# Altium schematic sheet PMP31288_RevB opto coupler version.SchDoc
size 431 x 279 mm; Date: Not shown in title block; ApprovedBy: Not shown in title block; CheckedBy: Not shown in title block; Author: Not shown in title block; CompanyName: Not shown in title block; Engineer: Not shown in title block; Organization: Not shown in title block; Address1: Not shown in title block; Address2: Not shown in title block; Address3: Not shown in title block; Address4: Not shown in title block; DocumentNumber: 2; Revision: Use project parameter SCH_Rev; SheetNumber: 2; SheetTotal: 3; PageSetup: Record=PageOptions¦CenterHorizontal=True¦CenterVertical=True¦PrintScale=1.00¦XCorrection=1.00¦YCorrection=1.00¦PrintKind=0¦BorderSize=5000000¦LeftOffset=0¦BottomOffset=0¦Orientation=2¦PaperLength=1000¦PaperWidth=1000¦Scale=100¦PaperSource=15¦PrintQuality=600¦MediaType=1¦DitherType=10¦PaperKind=Letter¦PrintScaleMode=1
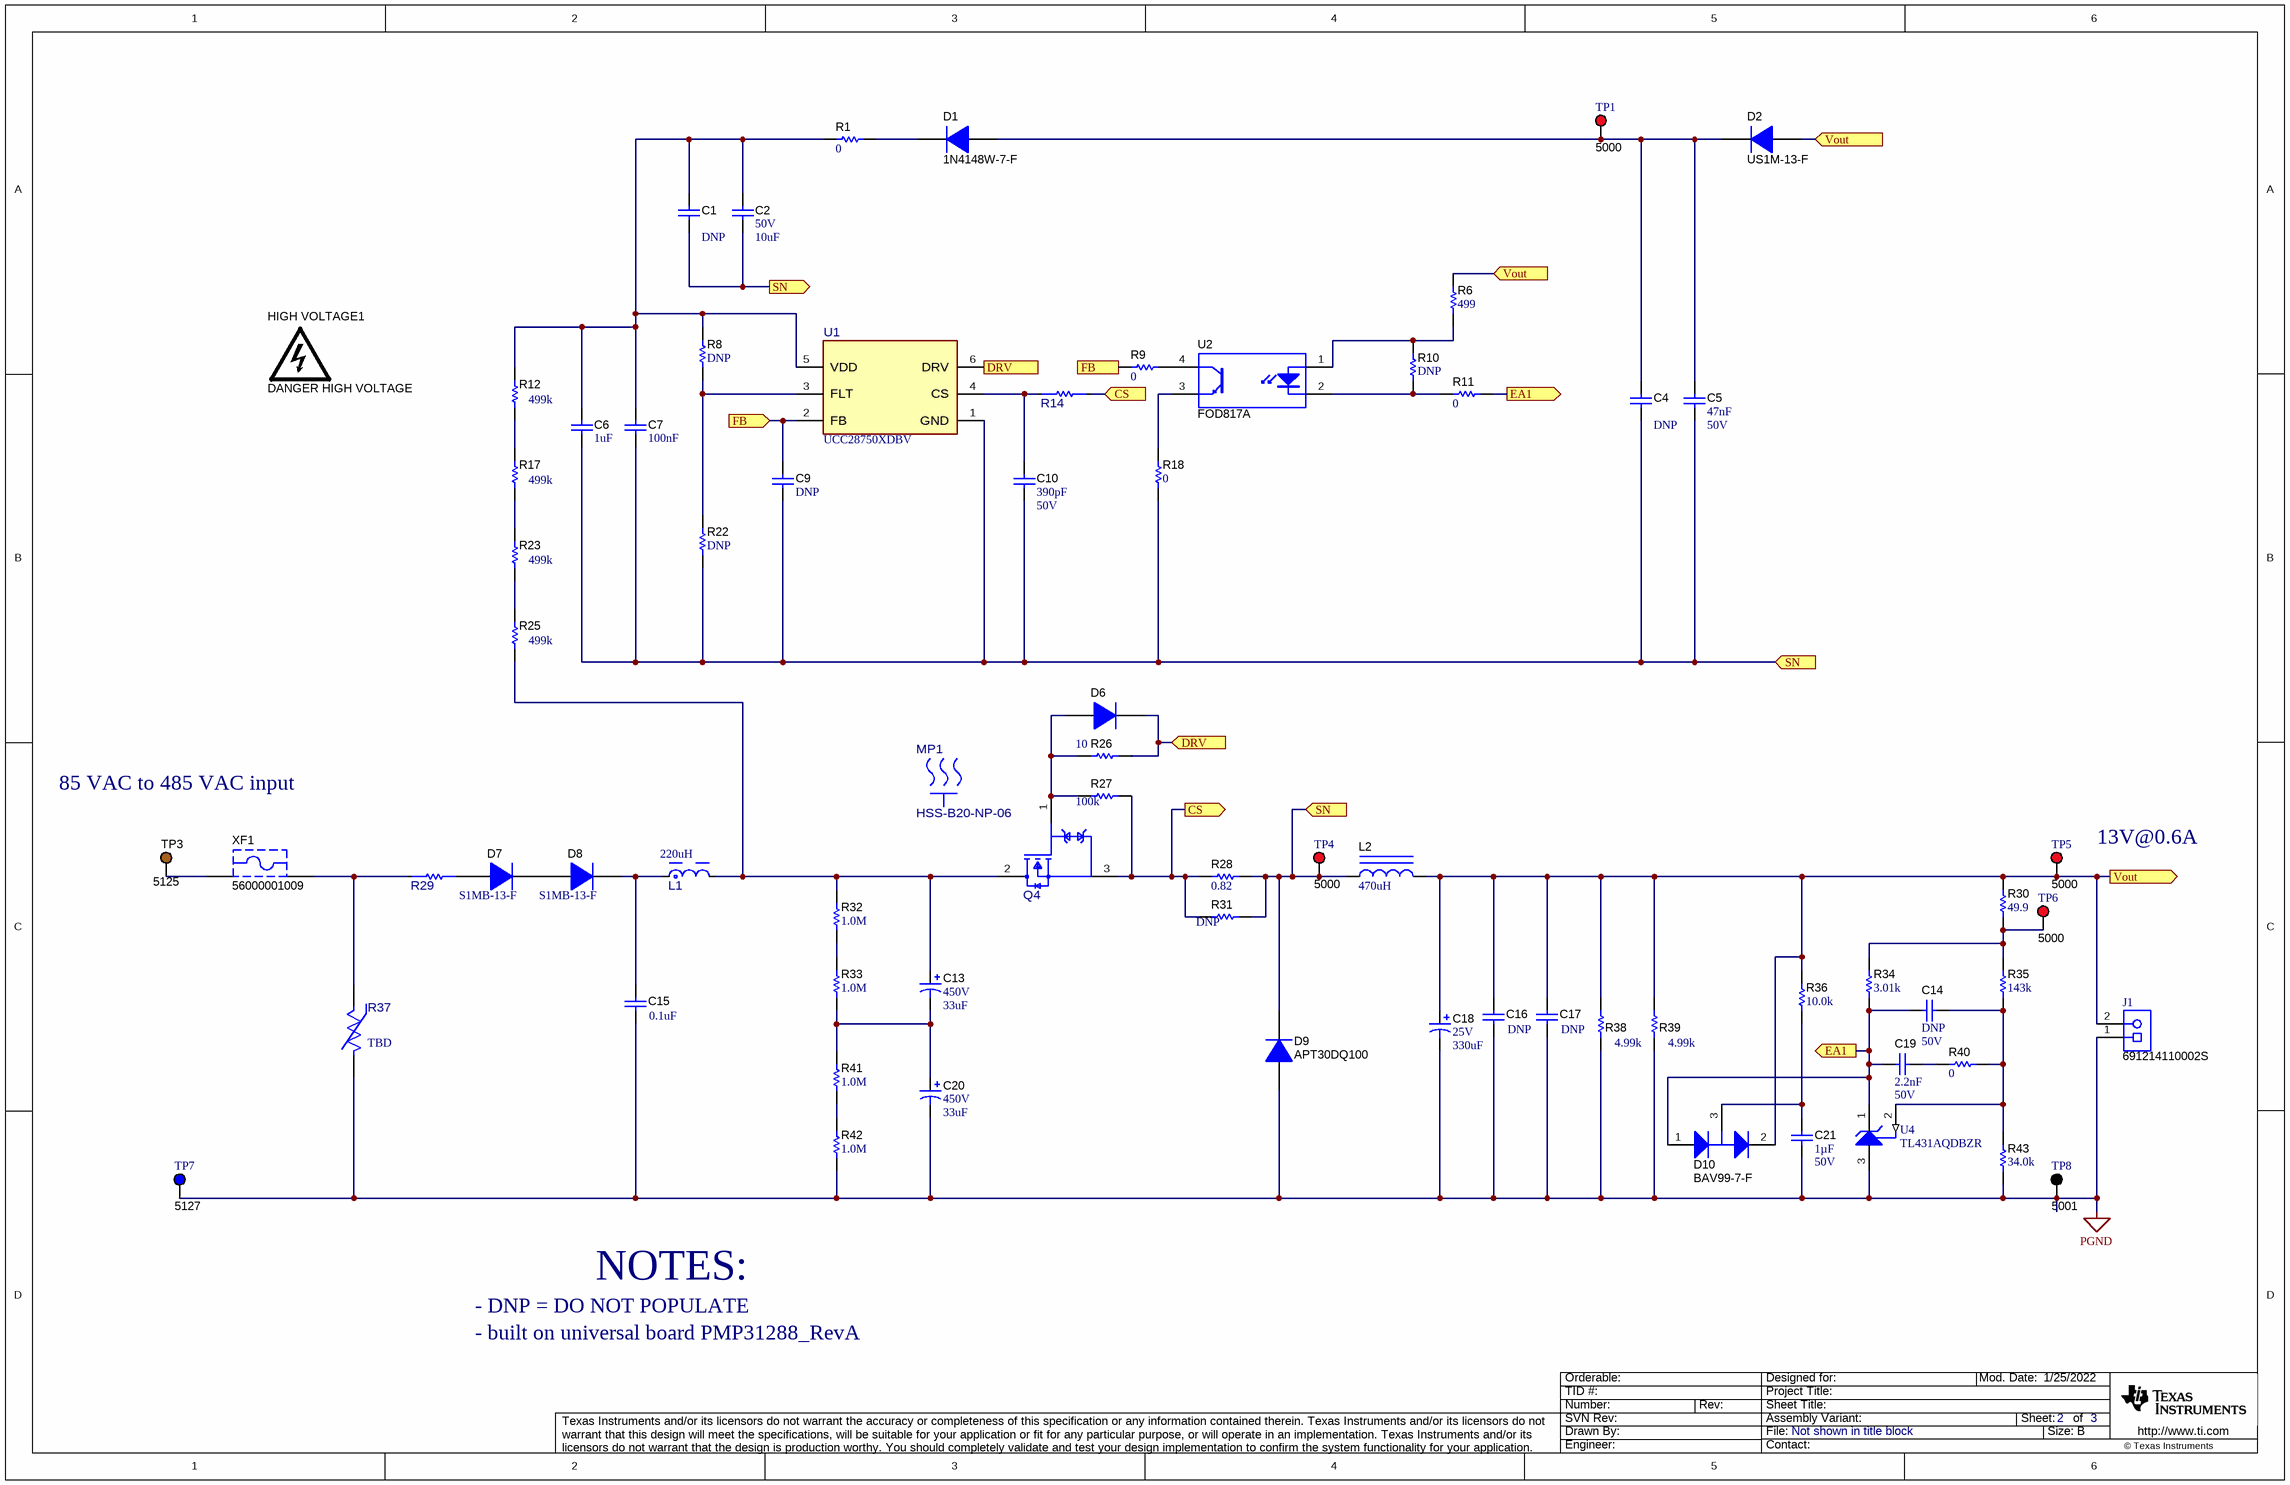
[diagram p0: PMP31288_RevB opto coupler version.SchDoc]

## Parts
C1  ValueDisplayed: DNP  [1210_180]  (hidden comment: DNPC3225X7R1H105K160AA)
C2  VDC_V: 50V  ValueDisplayed: 10uF  [1210_280]  (hidden comment: C3225X7R1H106M250AC)
C4  ValueDisplayed: DNP  [1210_180]  (hidden comment: DNPC3225X7R1H105K160AA)
C5  Cap_F: 47nF  VDC_V: 50V  [0805_HV]  (hidden comment: 08055C473KAT2A)
C6  Cap_F: 1uF  [0805_HV]  (hidden comment: C0805C104J5RACTU)
C7  Cap_F: 100nF  [0805_HV]  (hidden comment: C0805C104J5RACTU)
C9  DNP  [0603]
C10  Cap_F: 390pF  VDC_V: 50V  [0603]  (hidden comment: C0603C391K5RACTU)
C13  VDC_V: 450V  ValueDisplayed: 33uF  [UCS_1800x2000]  (hidden comment: UCS2W330MHD6)
C14  Cap_F: DNP  VDC_V: 50V  [0805_HV]  (hidden comment: DNP08055C473KAT2A)
C15  Cap_F: 0.1uF  [B32913_2650x700x1600]  (hidden comment: B32913C5104K000)
C16  value DNP  [1206]  (hidden comment: GCM31MR71E105KA37L)
C17  value DNP  [1206]  (hidden comment: GCM31MR71E105KA37L)
C18  VDC_V: 25V  ValueDisplayed: 330uF  [SM_RADIAL_F]  (hidden comment: EEE-FK1E331P)
C19  Cap_F: 2.2nF  VDC_V: 50V  [0603]  (hidden comment: GRM188R71H222KA01D)
C20  VDC_V: 450V  ValueDisplayed: 33uF  [UCS_1800x2000]  (hidden comment: UCS2W330MHD6)
C21  Cap_F: 1µF  VDC_V: 50V  [0805_HV]  (hidden comment: GRM21BR71H105KA12L)
D1  1N4148W-7-F  [SOD-123]
D2  US1M-13-F  [SMA]
D6  MMDL914-TP  [SOD-323]  (value not drawn)
D7  S1MB-13-F  [SMB]
D8  S1MB-13-F  [SMB]
D9  APT30DQ100  [TO-247-2]
D10  BAV99-7-F  [SOT-23L]
HIGH_VOLTAGE1  DANGER HIGH VOLTAGE  [IEC_HighVoltage_Small]  (no BOM)
J1  691214110002S  [FP-691214110002S_HDR2-MFG]
L1  value 220uH  [FP-7687480121_RADIAL-MFG]
L2  ValueDisplayed: 470uH  [mss1583]  (hidden comment: MSS1514V-474)
MP1  HSS-B20-NP-06  [FP-HSS-B20-NP-06_HEATSINK_19MM0_9MM52-MFG]
Q4  STP80N240K6  [FP-STP7N105K5_TO-220AB-MFG]  (value not drawn)
R1  ValueDisplayed: 0  [0805_HV]  (hidden comment: CRCW08050000Z0EAHP)
R6  ValueDisplayed: 499  [0603]  (hidden comment: RC0603FR-07499RL)
R8  DNP  [0603]
R9  ValueDisplayed: 0  [0603]  (hidden comment: CRCW06030000Z0EA)
R10  DNP  [0603]
R11  ValueDisplayed: 0  [0603]  (hidden comment: CRCW06030000Z0EA)
R12  value 499k  [1206]  (hidden comment: CRCW1206499KFKEA)
R14  CRCW06031K00FKEAC  [FP-CRCW06031K00FKEAC_0603-MFG]  (value not drawn)
R17  value 499k  [1206]  (hidden comment: CRCW1206499KFKEA)
R18  ValueDisplayed: 0  [0603]  (hidden comment: CRCW06030000Z0EA)
R22  DNP  [0603]
R23  value 499k  [1206]  (hidden comment: CRCW1206499KFKEA)
R25  value 499k  [1206]  (hidden comment: CRCW1206499KFKEA)
R26  value 10  [0805_HV]  (hidden comment: CRCW080510R0JNEA)
R27  value 100k  [0603]  (hidden comment: CRCW0603100KFKEA)
R28  ValueDisplayed: 0.82  [1206]  (hidden comment: ERJ-8RQFR82V)
R29  Z35092238209J6BC10_VM  [FP-Z35092238209J6BC10_VM_AXIAL-MFG]  (value not drawn)
R30  ValueDisplayed: 49.9  [0603]  (hidden comment: RC0603FR-0749R9L)
R31  DNP  [1206]
R32  ValueDisplayed: 1.0M  [1206]  (hidden comment: CRCW12061M00JNEA)
R33  ValueDisplayed: 1.0M  [1206]  (hidden comment: CRCW12061M00JNEA)
R34  ValueDisplayed: 3.01k  [0603]  (hidden comment: RC0603FR-073K01L)
R35  ValueDisplayed: 143k  [0603]  (hidden comment: CRCW0603143KFKEA)
R36  ValueDisplayed: 10.0k  [0603]  (hidden comment: RCG060310K0FKEA)
R37  Part Number: TBD  [FP-V20H510AUTO_RADIAL-MFG]  (hidden comment: V20H510AUTO)
R38  Res_ohm: 4.99k  [FP-CRCW08054K99FKEAHP_0805-IPC_B]  (hidden comment: CRCW08054K99FKEAHP)
R39  Res_ohm: 4.99k  [FP-CRCW08054K99FKEAHP_0805-IPC_B]  (hidden comment: CRCW08054K99FKEAHP)
R40  ValueDisplayed: 0  [0603]  (hidden comment: CRCW06030000Z0EA)
R41  ValueDisplayed: 1.0M  [1206]  (hidden comment: CRCW12061M00JNEA)
R42  ValueDisplayed: 1.0M  [1206]  (hidden comment: CRCW12061M00JNEA)
R43  ValueDisplayed: 34.0k  [0603]  (hidden comment: RC0603FR-0734KL)
TP1  5000  [Keystone5000]
TP3  5125  [Keystone5125]
TP4  5000  [Keystone5000]
TP5  5000  [Keystone5000]
TP6  5000  [Keystone5000]
TP7  5127  [Keystone5127]
TP8  5001  [Keystone5001]
U1  UCC28750XDBV  [DBV0006A-MFG]
U2  FOD817A  [DIP-4]
U4  TL431AQDBZR  [DBZ0003A_N]
XF1  56000001009  [FuseHolder_560000010]

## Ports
CS (in), CS (out), DRV (in), DRV (out), EA1 (out), FB (in), FB (out), SN (in), SN (out), Vout (in), Vout (out)

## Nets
PGND: C15.2 C16.2 C17.2 C18.2(-) C20.2(-) C21.2 D9.2(A) J1.1 R37.1 R38.1 R39.1 R42.1 R43.1 TP7.1 TP8.1 U4.3(ANODE)
CS: Q4.3(S) R14.2 R27.2 R28.1 R31.2 ; port CS
DRV: D6.1(K) R26.2 U1.6(DRV) ; port DRV
EA1: C14.2 C19.2 D10.1(A) R11.1 R34.1 U4.1(CATHODE) ; port EA1
FB: C9.1 R9.2 U1.2(FB) ; port FB
SN: C1.2 C2.2 C4.2 C5.2 C6.2 C7.2 C9.2 C10.2 D9.1(K) L2.1 R18.1 R22.1 R28.2 R31.1 TP4.1 U1.1(GND) ; port SN
Vout: C16.1 C17.1 C18.1(+) D2.2(A) D10.2(K) J1.2 L2.2 R6.2 R30.2 R36.2 R38.2 R39.2 TP5.1 ; port Vout
NetC1_1: C1.1 C2.1 C6.1 C7.1 R1.2 R8.2 R12.2 U1.5(VDD)
NetC4_1: C4.1 C5.1 D1.2(A) D2.1(K) TP1.1
NetC10_1: C10.1 R14.1 U1.4(CS)
NetC13_1: C13.1(+) L1.2 Q4.2(D) R25.1 R32.2
NetC13_2: C13.2(-) C20.1(+) R33.1 R41.2
NetC14_1: C14.1 R35.1 R40.1 R43.2 U4.2(REF)
NetC15_1: C15.1 D8.1(K) L1.1
NetC19_1: C19.1 R40.2
NetC21_1: C21.1 D10.3(C) R36.1
NetD1_1: D1.1(K) R1.1
NetD6_2: D6.2(A) Q4.1(G) R26.1 R27.1
NetD7_1: D7.1(K) D8.2(A)
NetD7_2: D7.2(A) R29.2
NetR6_1: R6.1 R10.2 U2.1(A)
NetR8_1: R8.1 R22.2 U1.3(FLT)
NetR9_1: R9.1 U2.4(C)
NetR10_1: R10.1 R11.2 U2.2(K)
NetR12_1: R12.1 R17.2
NetR17_1: R17.1 R23.2
NetR18_2: R18.2 U2.3(E)
NetR23_1: R23.1 R25.2
NetR29_1: R29.1 R37.2 XF1.1
NetR30_1: R30.1 R34.2 R35.2 TP6.1
NetR32_1: R32.1 R33.2
NetR41_1: R41.1 R42.2
NetTP3_1: TP3.1 XF1.2

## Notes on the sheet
- 85 VAC to 485 VAC input
- (near TP5) 13V@0.6A
- - DNP = DO NOT POPULATE
- NOTES:
- - built on universal board PMP31288_RevA

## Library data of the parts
C1 C4 = CMP-0009119-1: CAP, CERM,; Manufacturer: TDK; TaMin_C: -55°C; ESR_ohm: 7.168m; Polarized: N; TempCo: X7R; SizeAreaWB_mm2: 14.7; Value1: 0.007168 ohm; U/M: EA; Value: DNP; TaMax_C: 125°C; Tolerance_%: 10%; SizeZ_mm: 1.8; SizeX_mm: 3.2; SizeY_mm: 2.5; Value2: 50V; SizeArea_mm2: 8; Cap_F: 1µF; IRMS_A: 2.7503A; AEC Category: Q200
C2 = CMP-0009120-1: CAP, CERM, 10 uF, 50 V, +/- 20%, X7R, 1210; Manufacturer: TDK; TaMin_C: -55°C; Polarized: N; SizeAreaWB_mm2: 14.7; Value1: Unknown; U/M: EA; Value: 10uF; TaMax_C: 125°C; SizeZ_mm: 2.8; SizeX_mm: 3.2; SizeY_mm: 2.5; Cap_Case: 1210; SizeArea_mm2: 8; Cap_F: 10µF; AEC Category: Q200
C5 = CMP-0007659-2: CAP, CERM, 0.047 uF, 50 V, +/- 10%, X7R, 0805; Manufacturer: AVX; TaMin_C: -55°C; ESR_ohm: 35m; Polarized: N; SizeAreaWB_mm2: 6.75; Value1: 0.035 ohm; U/M: EA; TaMax_C: 125°C; SizeZ_mm: 1.45; SizeX_mm: 2; SizeY_mm: 1.25; Cap_Case: 0805; SizeArea_mm2: 2.5; AEC Category: Q200
C6 = CMP-0007721-2: DNP; Manufacturer: Kemet; TaMin_C: -55°C; ESR_ohm: 64m; Polarized: N; TempCo: X7R; SizeAreaWB_mm2: 6.75; Value1: 0.064 ohm; U/M: EA; Value: 1uF; TaMax_C: 125°C; Tolerance_%: 5%; SizeZ_mm: 1.45; SizeX_mm: 2; SizeY_mm: 1.25; Cap_Case: 0805; Value2: 50V; SizeArea_mm2: 2.5; IRMS_A: 1.64A; AEC Category: Q200
C7 = CMP-0007721-2: CAP, CERM, 0.1 uF, 50 V, +/- 5%, X7R, 0805; Manufacturer: Kemet; TaMin_C: -55°C; ESR_ohm: 64m; Polarized: N; SizeAreaWB_mm2: 6.75; Value1: 0.064 ohm; U/M: EA; Value: 0.1uF; TaMax_C: 125°C; SizeZ_mm: 1.45; SizeX_mm: 2; SizeY_mm: 1.25; Cap_Case: 0805; Value2: 50V; SizeArea_mm2: 2.5; IRMS_A: 1.64A; AEC Category: Q200
C9 = CMP-0007144-4: CAP, CERM,; Manufacturer: MuRata; TaMin_C: -55°C; ESR_ohm: 20m; Polarized: N; TempCo: X7R; SizeAreaWB_mm2: 4.68; Value1: 0.02 ohm; U/M: EA; TaMax_C: 125°C; Tolerance_%: 10%; SizeZ_mm: 1; SizeX_mm: 1.6; SizeY_mm: 0.8; Value2: 50V; SizeArea_mm2: 1.28; IRMS_A: 1.84A
C10 = CMP-0006933-5: CAP, CERM, 390 pF, 50 V, +/- 10%, X7R, 0603; Manufacturer: Kemet; TaMin_C: -55°C; Polarized: N; SizeAreaWB_mm2: 4.68; Value1: Unknown; U/M: EA; Value: 390pF; TaMax_C: 125°C; SizeZ_mm: 1; SizeX_mm: 1.6; SizeY_mm: 0.8; SizeArea_mm2: 1.28; AEC Category: Q200
C13 C20 = CMP-0010243-2: CAP, AL, 33 uF, 450 V, +/- 20%, TH; Manufacturer: Nichicon; TaMin_C: -25°C; Polarized: Y; SizeAreaWB_mm2: 400; Value1: Unknown; U/M: EA; Value: 33uF; TaMax_C: 105°C; SizeZ_mm: 21.5; SizeX_mm: 18; Cap_Case: 18x20mm; SizeArea_mm2: 324; CompType: Capacitor; AEC Qualified: N; Cap_F: 33µF; IRMS_A: 980mA; AEC Category: Q200
C14 = CMP-0007659-2: CAP, CERM,; Manufacturer: AVX; TaMin_C: -55°C; ESR_ohm: 35m; Polarized: N; TempCo: X7R; SizeAreaWB_mm2: 6.75; U/M: EA; Value: DNP; TaMax_C: 125°C; Tolerance_%: 10%; SizeZ_mm: 1.45; SizeX_mm: 2; SizeY_mm: 1.25; Cap_Case: 0805; SizeArea_mm2: 2.5; ValueDisplayed: 0.047uF
C15 = CMP-0012372-3: CAP, Film, 0.1 uF, 1000 V, +/- 10%, TH; Manufacturer: TDK; TaMin_C: -40°C; Polarized: N; SizeAreaWB_mm2: 256.5; Value1: Unknown; Value: 0.1uF; TaMax_C: 110°C; SizeZ_mm: 16; SizeX_mm: 26.5; SizeY_mm: 7; Cap_Case: 26.5x7x16mm; Value2: 1000V; SizeArea_mm2: 185.5; VDC_V: 1kV; AEC Category: Q200
C16 C17 = CMP-0008817-1: DNP; Manufacturer: MuRata; TaMin_C: -55°C; Polarized: N; TempCo: X7R; SizeAreaWB_mm2: 10.92; Value1: Unknown; U/M: EA; TaMax_C: 125°C; Tolerance_%: 10%; SizeZ_mm: 1.35; SizeX_mm: 3.2; SizeY_mm: 1.6; Value2: 25V; SizeArea_mm2: 5.12; AEC Qualified: Y; Cap_F: 1µF; AEC Grade: 1; AEC Category: Q200
C18 = CMP-0010717-1: CAP, AL, 330 uF, 25 V, +/- 20%, 0.16 ohm, AEC-Q200 Grade 2, SMD; Manufacturer: Panasonic; TaMin_C: -55°C; ESR_ohm: 0.16; Polarized: Y; SizeAreaWB_mm2: 123.6; U/M: EA; Value: 330uF; TaMax_C: 105°C; SizeZ_mm: 10.2; SizeX_mm: 10; SizeY_mm: 8.3; Cap_Case: F; SizeArea_mm2: 83; CompType: Capacitor; Cap_F: 330µF; IRMS_A: 600mA; AEC Grade: 2; AEC Category: Q200
C19 = CMP-0007443-4: CAP, CERM, 2200 pF, 50 V, +/- 10%, X7R, 0603; Manufacturer: MuRata; TaMin_C: -55°C; Polarized: N; SizeAreaWB_mm2: 4.68; Value1: Unknown; U/M: EA; Value: 2200pF; TaMax_C: 125°C; SizeZ_mm: 1; SizeX_mm: 1.6; SizeY_mm: 0.8; SizeArea_mm2: 1.28; AEC Category: Q200
C21 = CMP-0008350-2: CAP, CERM, 1 uF, 50 V, +/- 10%, X7R, 0805; Manufacturer: MuRata; TaMin_C: -55°C; Polarized: N; SizeAreaWB_mm2: 6.75; Value1: Unknown; U/M: EA; Value: 1uF; TaMax_C: 125°C; SizeZ_mm: 1.45; SizeX_mm: 2; SizeY_mm: 1.25; Cap_Case: 0805; SizeArea_mm2: 2.5; AEC Category: Q200
D1 = CMP-0029001-1: Diode, Ultrafast, 100 V, 0.15 A, SOD-123; Manufacturer: Diodes Inc.; Io_A: 150mA; Green_Lifecycle: Active; SizeAreaWB_mm2: 13.095; Vr_V: 100V; Green_REACh: Passed; Value1: 0.15A; TJmax_C: 150°C; U/M: EA; Value: 100V; SizeZ_mm: 1.35; SizeX_mm: 3.85; SizeY_mm: 1.7; Vf_V: 1.25V; SizeArea_mm2: 6.545; AEC Category: Q101
D2 = CMP-0076882-2: Diode, Ultrafast, 1000 V, 1 A, SMA; Manufacturer: Diodes Inc.; AEC Category: Q101; Value2: 1.7V; SizeZ_mm: 2.87; Green_REACh: Incomplete; Value: 1000V; Value1: 1A; SizeAreaWB_mm2: 37.3428; Green_Lifecycle: Not Set; RJC_CperW: 30.0; SizeX_mm: 5.59; SizeArea_mm2: 16.3228; Vr_V: 1kV; TJmax_C: 150°C; SizeY_mm: 2.92
D6 = CMP-0029045-1: Diode, Switching, 100 V, 0.2 A, SOD-323; Manufacturer: Micro Commercial Components; Io_A: 200mA; Green_Lifecycle: Not Set; SizeAreaWB_mm2: 8.695; Vr_V: 100V; Green_REACh: Incomplete; Value1: 0.2A; TJmax_C: 150°C; U/M: EA; Value: 100V; SizeZ_mm: 1; SizeX_mm: 2.7; SizeY_mm: 1.35; Vf_V: 1V; SizeArea_mm2: 3.645; AEC Category: Q101
D7 D8 = CMP-0077102-2: Diode, Standard Recovery Rectifier, 1000 V, 1 A, SMB; Manufacturer: Diodes Inc.; Vr_V: 1kV; Value1: 1A; SizeZ_mm: 2.6; TJmax_C: 150°C; Vf_V: 1.1V; Value: 1000V; SizeArea_mm2: 21.336; SizeY_mm: 3.81; AEC Category: Q101; AEC Qualified: N; SizeAreaWB_mm2: 44.156; SizeX_mm: 5.6
D9 = CMP-0077054-3: Diode, Ultrafast, 1000 V, 30 A, TH; Manufacturer: Microsemi; Value2: 2.4V; SizeZ_mm: 25.96; Green_Lifecycle: Not Set; SizeAreaWB_mm2: 125.125; AEC Category: Q101; Value: 1000V; TJmax_C: 175°C; SizeY_mm: 5.0; Value1: 30A; Green_REACh: Incomplete; SizeArea_mm2: 79.375; SizeX_mm: 15.875; RJC_CperW: 0.8
D10 = CMP-0076900-2: Diode, Switching, 75 V, 0.3 A, SOT-23; Manufacturer: Diodes Inc.; SizeY_mm: 3.0; Io_A: 300mA; TJmax_C: 150°C; Green_Lifecycle: Active; Vr_V: 75V; Green_REACh: Passed; Vf_V: 1.25V; SizeAreaWB_mm2: 14.0; Value1: 0.3A; SizeX_mm: 2.5; SizeZ_mm: 1.1; Value: 75V; AEC Category: Q101; SizeArea_mm2: 7.5
HIGH_VOLTAGE1 = CMP-0074835-1: IEC 61010-1 High Voltage Warning; SymbolCreator: a0412235
J1 = CMP-0093089-2: 2 Position Wire to Board Terminal Block Horizontal with Board 0.138" (3.50mm) Through Hole; Manufacturer: Wurth; ContactFinish: Tin,Nickel; AEC Qualified: No; Max Wire Gauge: 16; Voltage_V: 300V; SizeZ_mm: 9.2mm; Current_A: 10A; DUT-Pitch_mm: 3.5mm; Min Wire Gauge: 30; Conn Gender: Female; Row_Count: 1; Is Female: yes
L1 = CMP-0095920-1: WE-TI HV Radial Leaded Wire Wound Inductor (High Voltage) 220µH; Manufacturer: Wurth; AEC Qualified: No; Isat: 2A; Tolerance_%: 10%; TaMin_C: -40°C; Test Frequency: 100kHz; DCR_ohm: 0.18; TaMax_C: +85°C; Self Resonant Frequency: 3.1MHz
L2 = CMP-0061946-2: Inductor, Drum Core, Ferrite, 470 uH,; Manufacturer: Coilcraft; Isat: 2.2A @ 30% inductance drop; Irms: 1.35A @ 40C rise; Green_Lifecycle: Not Set; SizeAreaWB_mm2: 292.41; Green_REACh: Incomplete; Value: 470uH; SizeZ_mm: 8.6; SizeX_mm: 15.1; Value2: 1.35A; SizeArea_mm2: 228.01; Ind_H: 470µH; AEC Qualified: N
MP1 = CMP-0091664-1: Heat Sink TO-220 Aluminum 2.9W @ 75°C Board Level; Manufacturer: CUI Devices; AEC Qualified: No; Thermal Resistance Forced Air Flow: 5.84°C/W; Natural Thermal Resistance: 31.94°C/W; SizeZ_mm: 19.5mm
Q4 = CMP-0088481-1: N-Channel 800V Through Hole TO-220; Manufacturer: STMicroelectronics; QgTyp_nC: 11nC @ 10V; Standoff Height: 3.5mm; Threshold Vgs Max: 5V; SizeZ_mm: 19.68mm; Reverse Recovery Time: 370ns; Rdson45_ohm: 1.4; Turn Off Delay Time: 43ns; VdsMax_V: 1.6V; Drain To Source Breakdown Voltage: 1050V; Number Of Channels: 1; IdsMax_A: 4A; AEC Qualified: No; ChMode: False; TJmax_C: +150°C; Turn On Delay Time: 17.5ns
R1 = CMP-0020443-2: RES, 0, 5%, 0.333 W, 0805; Manufacturer: Vishay-Dale; Power_W: 333mW; TempCo: 200 ppm/C; Value_Code: 0000; U/M: EA; Value: 0; EIA_Code: E24; SizeX_mm: 2; SizeY_mm: 1.25; SizeZ_mm: 1.45; Value2: 0.333W; SizeArea_mm2: 2.5; AEC Category: Q200
R6 = CMP-0023141-5: RES, 499, 1%, 0.1 W, 0603; Manufacturer: Yageo; Power_W: 100mW; TempCo: 100 ppm/C; Value_Code: 499R; Value: 499; EIA_Code: E96; SizeX_mm: 1.6; SizeY_mm: 0.8; SizeZ_mm: 1; Value2: 0.1W; SizeArea_mm2: 1.28; AEC Qualified: N; VDC_V: 75V; AEC Category: Q200; SizeAreaWB_mm2: 4.68
R8 R10 R22 = CMP-0022796-4: RES,; Manufacturer: Yageo; PartNumber: RC0603FR-07140KL; Power_W: 100mW; TempCo: 100 ppm/C; Value_Code: 140k; Value1: 1%; EIA_Code: E96; SizeX_mm: 1.6; SizeY_mm: 0.8; SizeZ_mm: 1; Value2: 0.1W; SizeArea_mm2: 1.28; AEC Qualified: N; VDC_V: 75V; AEC Category: Q200; SizeAreaWB_mm2: 4.68
R9 R11 R18 R40 = CMP-0025697-1: RES, 0, 5%, 0.1 W, 0603; Manufacturer: Vishay-Dale; Power_W: 100mW; TempCo: 200 ppm/C; Value_Code: 0000; U/M: EA; Value: 0; EIA_Code: E24; SizeX_mm: 1.6; SizeY_mm: 0.8; SizeZ_mm: 1; Value2: 0.1W; SizeArea_mm2: 1.28; VDC_V: 75V; AEC Category: Q200
R12 R17 R23 R25 = CMP-0017016-3: RES, 499 k, 1%, 0.25 W, AEC-Q200 Grade 0, 1206; Manufacturer: Vishay-Dale; Power_W: 250mW; TempCo: 100 ppm/C; EIA_Code: E96; SizeX_mm: 3.2; SizeY_mm: 1.6; SizeZ_mm: 1.35; Value2: 0.25W; SizeArea_mm2: 5.12; AEC Qualified: Y; VDC_V: 200V; AEC Category: Q200; AEC Grade: 0
R14 = CMP-0090742-1: 1 kOhms ±1% 0.1W, 1/10W Chip Resistor 0603 (1608 Metric) Thick Film; Manufacturer: Vishay; Value: 1k; AEC Qualified: No; TempCo: 100ppm/°C; Power_W: 100mW; SizeZ_mm: 0.55mm; VDC_V: 75V
R26 = CMP-0020448-1: RES, 10, 5%, 0.125 W, 0805; Manufacturer: Vishay-Dale; Power_W: 125mW; TempCo: 200 ppm/C; Value_Code: 10R0; U/M: EA; EIA_Code: E24; SizeX_mm: 2; SizeY_mm: 1.25; SizeZ_mm: 1.45; Value2: 0.125W; SizeArea_mm2: 2.5; VDC_V: 150V; AEC Category: Q200
R27 = CMP-0021990-3: RES, 100 k, 1%, 0.1 W, 0603; Manufacturer: Vishay-Dale; Power_W: 100mW; TempCo: 100 ppm/C; U/M: EA; EIA_Code: E96; SizeX_mm: 1.6; SizeY_mm: 0.8; SizeZ_mm: 1; Value2: 0.1W; SizeArea_mm2: 1.28; VDC_V: 75V; AEC Category: Q200
R28 = CMP-0017794-3: RES, 0.82, 1%, 0.25 W, AEC-Q200 Grade 0, 1206; Manufacturer: Panasonic; Power_W: 250mW; TempCo: 250 ppm/C; Value_Code: R820; Value: 0.82; EIA_Code: E96; SizeX_mm: 3.2; SizeY_mm: 1.6; SizeZ_mm: 1.35; Value2: 0.25W; SizeArea_mm2: 5.12; AEC Qualified: Y; AEC Category: Q200; AEC Grade: 0; SizeAreaWB_mm2: 10.92
R29 = CMP-0091179-1: Industrial Axial Cemented Leaded Wirewound Resistors  5% 6W; Manufacturer: Vishay; AEC Qualified: No; Value: TBD
R30 = CMP-0023143-5: RES, 49.9, 1%, 0.1 W, 0603; Manufacturer: Yageo; Power_W: 100mW; TempCo: 100 ppm/C; Value_Code: 49R9; Value: 49.9; EIA_Code: E96; SizeX_mm: 1.6; SizeY_mm: 0.8; SizeZ_mm: 1; Value2: 0.1W; SizeArea_mm2: 1.28; AEC Qualified: N; VDC_V: 75V; AEC Category: Q200; SizeAreaWB_mm2: 4.68
R31 = CMP-0017792-3: RES, 0.56, 1%, 0.25 W, AEC-Q200 Grade 0, 1206; Manufacturer: Panasonic; Power_W: 250mW; TempCo: 250 ppm/C; Value_Code: R560; EIA_Code: E96; SizeX_mm: 3.2; SizeY_mm: 1.6; SizeZ_mm: 1.35; Value2: 0.25W; SizeArea_mm2: 5.12; AEC Qualified: Y; AEC Category: Q200; ValueDisplayed: 0.56; AEC Grade: 0; SizeAreaWB_mm2: 10.92
R32 R33 R41 R42 = CMP-0018610-3: RES, 1.0 M, 5%, 0.25 W, AEC-Q200 Grade 0, 1206; Manufacturer: Vishay-Dale; Power_W: 250mW; TempCo: 200 ppm/C; Value_Code: 1M00; Value: 1.0Meg; EIA_Code: E24; Res_ohm: 1M; SizeX_mm: 3.2; SizeY_mm: 1.6; SizeZ_mm: 1.35; Value2: 0.25W; SizeArea_mm2: 5.12; AEC Qualified: Y; VDC_V: 200V; AEC Category: Q200; AEC Grade: 0
R34 = CMP-0023076-5: RES, 3.01 k, 1%, 0.1 W, 0603; Manufacturer: Yageo; Power_W: 100mW; TempCo: 100 ppm/C; Value_Code: 3k01; Value: 3.01k; EIA_Code: E96; SizeX_mm: 1.6; SizeY_mm: 0.8; SizeZ_mm: 1; Value2: 0.1W; SizeArea_mm2: 1.28; AEC Qualified: N; VDC_V: 75V; AEC Category: Q200; SizeAreaWB_mm2: 4.68
R35 = CMP-0022050-4: RES, 143 k, 1%, 0.1 W, AEC-Q200 Grade 0, 0603; Manufacturer: Vishay-Dale; Power_W: 100mW; TempCo: 100 ppm/C; Value: 143k; EIA_Code: E96; SizeX_mm: 1.6; SizeY_mm: 0.8; SizeZ_mm: 1; Value2: 0.1W; SizeArea_mm2: 1.28; AEC Qualified: Y; VDC_V: 75V; AEC Category: Q200; AEC Grade: 0
R36 = CMP-0023337-3: RES, 10.0 k, 1%, 0.1 W, 0603; Manufacturer: Vishay Draloric; Power_W: 100mW; TempCo: 100 ppm/C; Value_Code: 10k0; U/M: EA; Value: 10.0k; EIA_Code: E96; Res_ohm: 10k; SizeX_mm: 1.6; SizeY_mm: 0.8; SizeZ_mm: 1; Value2: 0.1W; SizeArea_mm2: 1.28; AEC Qualified: N; VDC_V: 75V; AEC Category: Q200
R37 = CMP-0090617-1: 820V 10kA Varistor 1 Circuit Through Hole Disc 20mm; Manufacturer: Littelfuse; Varistor Voltage: 738V; TaMax_C: +125°C; ValueDisplayed: 350pF; Clamping Voltage: 1355V; AEC Qualified: Yes; Vc: 100A; TaMin_C: -40°C; AEC Grade: Grade 1; VDC_V: 670V; SizeZ_mm: 28mm
R38 R39 = CMP-0086412-2: Res Thick Film 0805 4.99K Ohm 1% 1/3W 100ppm/C Molded SMD SMD Paper T/R; Manufacturer: Vishay Dale; AEC Qualified: Yes; AEC Grade: Grade 0; SizeZ_mm: 0.6mm; VDC_V: 150V; Power_W: 500mW; TempCo: 100ppm/°C
R43 = CMP-0023045-5: RES, 34.0 k, 1%, 0.1 W, 0603; Manufacturer: Yageo; Power_W: 100mW; TempCo: 100 ppm/C; Value_Code: 34k0; Value: 34.0k; EIA_Code: E96; Res_ohm: 34k; SizeX_mm: 1.6; SizeY_mm: 0.8; SizeZ_mm: 1; Value2: 0.1W; SizeArea_mm2: 1.28; AEC Qualified: N; VDC_V: 75V; AEC Category: Q200; SizeAreaWB_mm2: 4.68
TP1 TP4-TP6 = CMP-0055137-2: Test Point, Miniature, Red, TH; Manufacturer: Keystone Electronics; Green_REACh: Passed; Green_Lifecycle: Active; ContactFinish: Silver; CNHeader: FALSE; CT: TRUE
TP3 = CMP-0055157-2: Test Point, Multipurpose, Brown, TH; Manufacturer: Keystone Electronics; CT: TRUE; Green_Lifecycle: Active; CNHeader: FALSE; ContactFinish: Silver; Green_REACh: Passed
TP7 = CMP-0055156-2: Test Point, Multipurpose, Blue, TH; Manufacturer: Keystone Electronics; CT: TRUE; ContactFinish: Silver; CNHeader: FALSE; Green_REACh: Passed; Green_Lifecycle: Active
TP8 = CMP-0055138-2: Test Point, Miniature, Black, TH; Manufacturer: Keystone Electronics; ContactFinish: Silver; CNHeader: FALSE; Green_Lifecycle: Active; Green_REACh: Passed; CT: TRUE
U1 = CMP-0001574-1: Continuous Conduction Mode (CCM) Secondary Side Regulated (SSR) Current-Mode Offline Flyback Controller; Manufacturer: Texas Instruments; SizeZ_mm: 1.45mm; AEC Qualified: No; Max Duty Cycle: 80%; Max Supply Voltage: 29.7V; Min Supply Voltage: 8V; Nominal Supply Current: 1.8-2mA; Number Of Outputs: 1; Standoff Height: 0mm; TJmax_C: +125°C
U2 = CMP-0006173-3: Optocoupler, 5 kV, 80-160% CTR, TH; Manufacturer: Fairchild Semiconductor; CTR (Max): 160%; SizeAreaWB_mm2: 71.064; CTR (Min): 80%; SizeZ_mm: 5; SizeX_mm: 8.8; SizeY_mm: 4.58; SizeArea_mm2: 40.304; Voltage_Isolation_Vrms: 5kV
U4 = CMP-0033157-1: Adjustable Precision Shunt Regulator, 34 ppm / degC, 100 mA, -40 to 125 degC, 3-pin SOT-23 (DBZ), Green (RoHS & no Sb/Br); Manufacturer: Texas Instruments; Temp Coeff(Max)(ppm/ degree C): 92; Min Iz for Regulation(uA): 600; Initial Accuracy @ 25/deg C(%): 1; VO Adj(Max)(V): 36; Temp Coeff(Typ)(ppm/ degree C): 34; VO Adj(Min)(V): 2.495; SubFamily: Shunt Voltage Reference; Rating: Catalog; Iout/Iz(Max)(mA): 100
XF1 = CMP-0003627-1: Fuse Holder, TR5, TH; Manufacturer: Littelfuse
